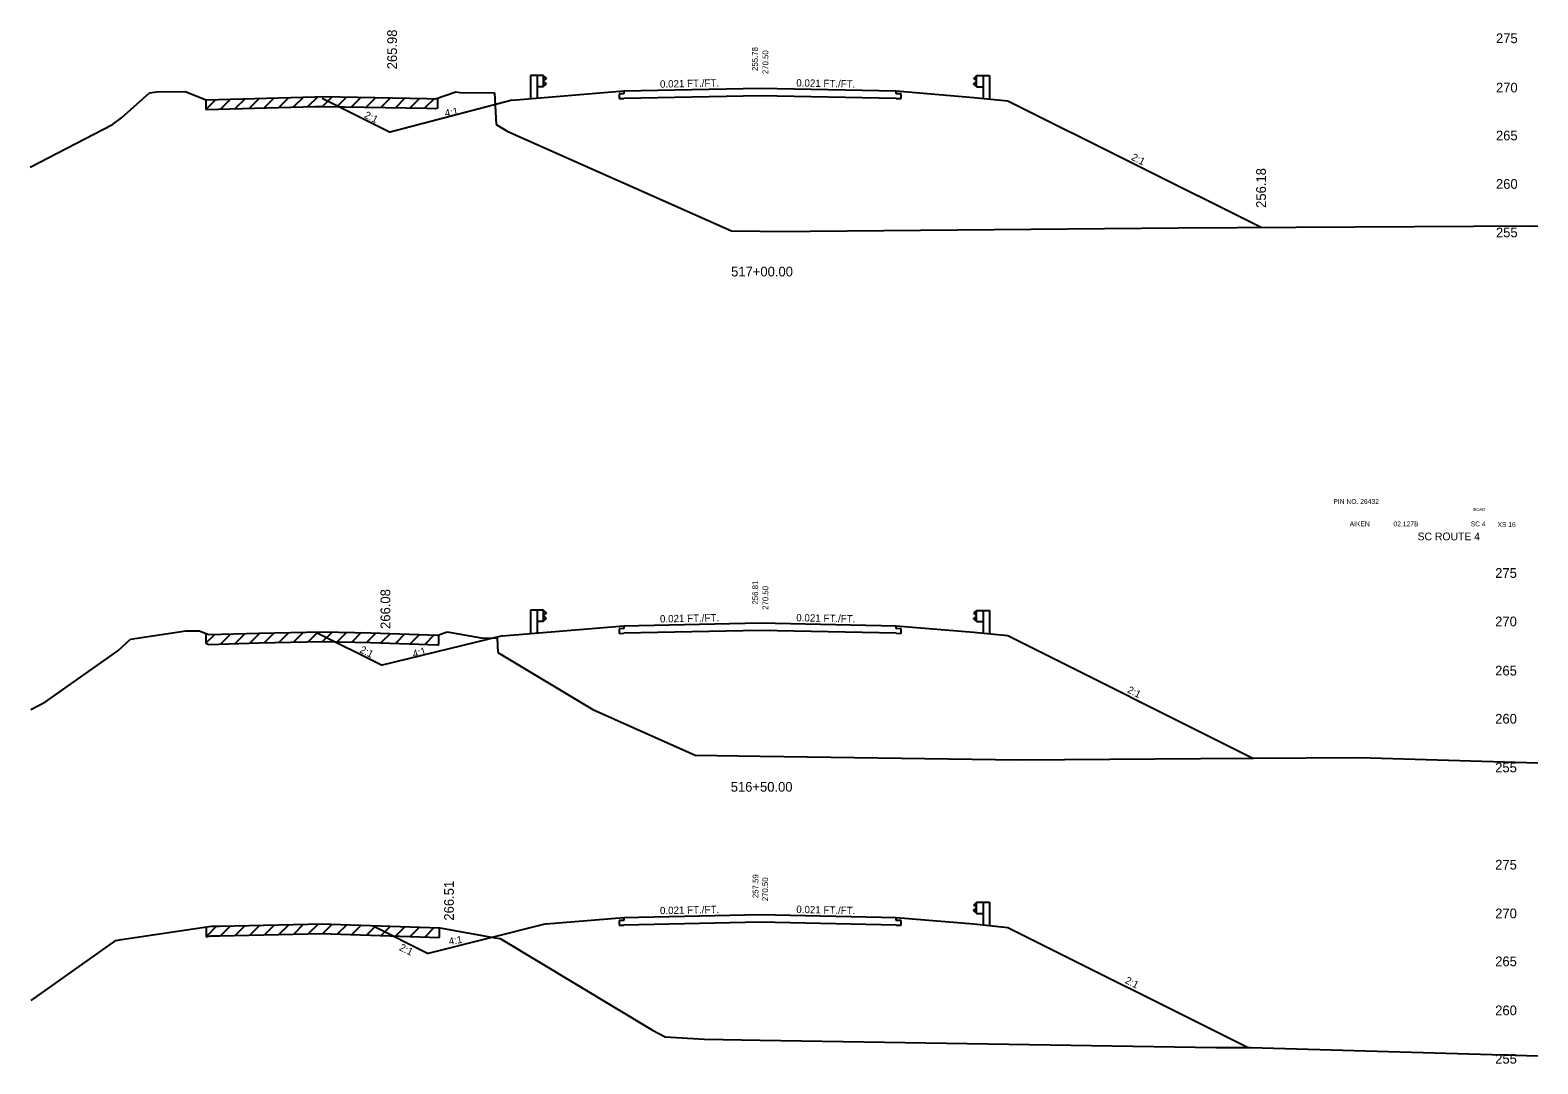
# Model space of a CAD drawing. Extents: x 883 to 1160, y 1002 to 4323.
# Drawn here: x 1004.9 to 1160, y 2770.2 to 2876.5 of the extents above; entities that cross this region are included whole.
import ezdxf

# ---------------------------------------------------------------- set-up
doc = ezdxf.new("R2010")
doc.units = 0
for name, color, linetype in [('Level 1', 7, 'Continuous'), ('Level 10', 7, 'Continuous'), ('Level 11', 7, 'Continuous'), ('Level 12', 7, 'Continuous'), ('Level 24', 7, 'Continuous'), ('Level 3', 7, 'Continuous'), ('Level 32', 7, 'Continuous'), ('Level 33', 7, 'Continuous'), ('Level 59', 7, 'Continuous'), ('Level 6', 7, 'Continuous'), ('Level 60', 7, 'Continuous'), ('Level 61', 7, 'Continuous'), ('Level 7', 7, 'Continuous')]:
    doc.layers.add(name, color=color, linetype=linetype)

msp = doc.modelspace()

# ---------------------------------------------------------------- linework, layer by layer
at = {"layer": 'Level 11'}
for p, q in [((1066, 2869.91), (1065.5, 2869.9)), ((1065.5, 2869.9), (1065.5, 2869.42)), ((1065.5, 2869.42), (1066, 2869.43)), ((1066, 2870.21), (1066, 2869.91)), ((1094, 2869.91), (1094, 2870.21)), ((1094.5, 2869.9), (1094, 2869.91)), ((1094, 2869.43), (1094.5, 2869.42)), ((1094.5, 2869.42), (1094.5, 2869.9)), ((1066, 2814.91), (1065.5, 2814.9)), ((1065.5, 2814.9), (1065.5, 2814.42)), ((1066, 2815.21), (1066, 2814.91)), ((1094, 2814.91), (1094, 2815.21)), ((1094.5, 2814.9), (1094, 2814.91)), ((1094.5, 2814.42), (1094.5, 2814.9)), ((1065.5, 2814.42), (1066, 2814.43)), ((1094, 2814.43), (1094.5, 2814.42)), ((1066, 2784.91), (1065.5, 2784.9)), ((1065.5, 2784.9), (1065.5, 2784.42)), ((1065.5, 2784.42), (1066, 2784.43)), ((1066, 2785.21), (1066, 2784.91)), ((1094, 2784.91), (1094, 2785.21)), ((1094.5, 2784.9), (1094, 2784.91)), ((1094, 2784.43), (1094.5, 2784.42)), ((1094.5, 2784.42), (1094.5, 2784.9))]:
    msp.add_line(p, q, dxfattribs=at)
at = {"layer": 'Level 12'}
for p, q in [((1080, 2869.72), (1066, 2869.43)), ((1094, 2869.43), (1080, 2869.72)), ((1080, 2814.72), (1066, 2814.43)), ((1094, 2814.43), (1080, 2814.72)), ((1080, 2784.72), (1066, 2784.43)), ((1094, 2784.43), (1080, 2784.72))]:
    msp.add_line(p, q, dxfattribs=at)
at = {"layer": 'Level 24'}
for p, q in [((1056.4, 2871.8), (1056.4, 2869.39)), ((1057.07, 2871.8), (1056.4, 2871.8)), ((1057.73, 2871.8), (1057.07, 2871.8)), ((1057.07, 2871.8), (1057.07, 2869.46)), ((1057.73, 2870.64), (1057.07, 2870.64)), ((1057.73, 2870.64), (1057.73, 2871.8)), ((1057.73, 2871.73), (1058, 2871.53)), ((1058, 2871.48), (1057.73, 2871.28)), ((1058, 2870.96), (1057.73, 2871.16)), ((1057.73, 2870.71), (1058, 2870.91)), ((1058, 2871.53), (1058, 2871.48)), ((1058, 2870.91), (1058, 2870.96)), ((1102.27, 2871.72), (1102, 2871.52)), ((1102, 2871.52), (1102, 2871.47)), ((1102, 2871.47), (1102.27, 2871.27)), ((1102, 2870.95), (1102.27, 2871.15)), ((1102, 2870.9), (1102, 2870.95)), ((1102.27, 2870.7), (1102, 2870.9)), ((1102.27, 2870.63), (1102.27, 2871.79)), ((1102.27, 2871.79), (1102.94, 2871.79)), ((1102.27, 2870.63), (1102.94, 2870.63)), ((1102.94, 2871.79), (1102.94, 2869.45)), ((1102.94, 2871.79), (1103.6, 2871.79)), ((1103.6, 2871.79), (1103.6, 2869.38)), ((1056.4, 2816.81), (1056.4, 2814.4)), ((1057.07, 2816.81), (1056.4, 2816.81)), ((1057.73, 2816.81), (1057.07, 2816.81)), ((1057.07, 2816.81), (1057.07, 2814.47)), ((1057.73, 2815.64), (1057.73, 2816.81)), ((1057.73, 2816.74), (1058, 2816.54)), ((1058, 2816.49), (1057.73, 2816.29)), ((1058, 2816.54), (1058, 2816.49)), ((1102.27, 2816.72), (1102, 2816.52)), ((1102, 2816.52), (1102, 2816.47)), ((1102, 2816.47), (1102.27, 2816.27)), ((1102.27, 2815.63), (1102.27, 2816.79)), ((1102.27, 2816.79), (1102.94, 2816.79)), ((1102.94, 2816.79), (1102.94, 2814.45)), ((1102.94, 2816.79), (1103.6, 2816.79)), ((1103.6, 2816.79), (1103.6, 2814.38)), ((1057.73, 2815.64), (1057.07, 2815.64)), ((1058, 2815.97), (1057.73, 2816.17)), ((1057.73, 2815.72), (1058, 2815.92)), ((1058, 2815.92), (1058, 2815.97)), ((1102, 2815.95), (1102.27, 2816.15)), ((1102, 2815.9), (1102, 2815.95)), ((1102.27, 2815.7), (1102, 2815.9)), ((1102.27, 2815.63), (1102.94, 2815.63)), ((1102.27, 2785.63), (1102.27, 2786.79)), ((1102.27, 2786.79), (1102.94, 2786.79)), ((1102.94, 2786.79), (1102.94, 2784.45)), ((1102.94, 2786.79), (1103.6, 2786.79)), ((1103.6, 2786.79), (1103.6, 2784.38)), ((1102.27, 2786.72), (1102, 2786.52)), ((1102, 2786.52), (1102, 2786.47)), ((1102, 2786.47), (1102.27, 2786.27)), ((1102, 2785.95), (1102.27, 2786.15)), ((1102, 2785.9), (1102, 2785.95)), ((1102.27, 2785.7), (1102, 2785.9)), ((1102.27, 2785.63), (1102.94, 2785.63))]:
    msp.add_line(p, q, dxfattribs=at)
at = {"layer": 'Level 59'}
for p, q in [((1066, 2870.21), (1080, 2870.5)), ((1080, 2870.5), (1094, 2870.21)), ((1066, 2815.21), (1080, 2815.5)), ((1080, 2815.5), (1094, 2815.21)), ((1066, 2785.21), (1080, 2785.5)), ((1080, 2785.5), (1094, 2785.21))]:
    msp.add_line(p, q, dxfattribs=at)
at = {"layer": 'Level 6'}
for p, q in [((1054.5, 2869.25), (1066, 2870.21)), ((1094, 2870.21), (1102, 2869.54)), ((1102, 2869.54), (1105.5, 2869.19)), ((1053.5, 2814.17), (1066, 2815.21)), ((1094, 2815.21), (1102, 2814.54)), ((1102, 2814.54), (1105.5, 2814.19)), ((1058, 2784.54), (1066, 2785.21)), ((1094, 2785.21), (1102, 2784.54)), ((1102, 2784.54), (1105.5, 2784.19))]:
    msp.add_line(p, q, dxfattribs=at)
at = {"layer": 'Level 60'}
for p, q in [((1014.32, 2867.43), (1017.18, 2870)), ((1017.18, 2870), (1017.91, 2870.11)), ((1017.91, 2870.11), (1020.87, 2870.15)), ((1020.87, 2870.15), (1023.01, 2869.29)), ((1023.01, 2869.29), (1034.2, 2869.61)), ((1034.2, 2869.61), (1035.02, 2869.62)), ((1035.02, 2869.62), (1045.76, 2869.42)), ((1045.76, 2869.42), (1046.6, 2869.39)), ((1046.6, 2869.39), (1048.72, 2870.13)), ((1048.72, 2870.13), (1049.15, 2870.06)), ((1049.15, 2870.06), (1052.67, 2870.01)), ((1052.67, 2870.01), (1052.85, 2866.76)), ((1004.92, 2862.36), (1013.38, 2866.76)), ((1013.38, 2866.76), (1014.32, 2867.43)), ((1052.85, 2866.76), (1054.06, 2866.03)), ((1054.06, 2866.03), (1077.07, 2855.82)), ((1077.07, 2855.82), (1080, 2855.78)), ((1080, 2855.78), (1081.39, 2855.76)), ((1081.39, 2855.76), (1122.99, 2856.13)), ((1122.99, 2856.13), (1159.46, 2856.32)), ((1159.46, 2856.32), (1160, 2856.3)), ((1013.93, 2812.63), (1015.25, 2813.82)), ((1015.25, 2813.82), (1020.95, 2814.67)), ((1020.95, 2814.67), (1022.31, 2814.69)), ((1022.31, 2814.69), (1023.29, 2814.29)), ((1023.29, 2814.29), (1028.44, 2814.44)), ((1028.44, 2814.44), (1035, 2814.57)), ((1035, 2814.57), (1039.95, 2814.48)), ((1039.95, 2814.48), (1046.84, 2814.25)), ((1046.84, 2814.25), (1047.82, 2814.59)), ((1047.82, 2814.59), (1051.32, 2813.96)), ((1051.32, 2813.96), (1052.95, 2813.94)), ((1052.95, 2813.94), (1053.03, 2812.44)), ((1006.51, 2807.38), (1013.93, 2812.63)), ((1053.03, 2812.44), (1062.8, 2806.59)), ((1005, 2806.59), (1006.51, 2807.38)), ((1062.8, 2806.59), (1073.33, 2801.91)), ((1073.33, 2801.91), (1080, 2801.81)), ((1080, 2801.81), (1106.66, 2801.4)), ((1106.66, 2801.4), (1125.29, 2801.57)), ((1125.29, 2801.57), (1141.62, 2801.66)), ((1141.62, 2801.66), (1160, 2801.12)), ((1014.31, 2782.93), (1023.53, 2784.3)), ((1023.53, 2784.3), (1024.38, 2784.31)), ((1024.38, 2784.31), (1034.99, 2784.54)), ((1034.99, 2784.54), (1035.85, 2784.51)), ((1035.85, 2784.51), (1047.05, 2784.14)), ((1047.05, 2784.14), (1052.74, 2783.12)), ((1005.03, 2776.68), (1013.74, 2782.85)), ((1013.74, 2782.85), (1014.31, 2782.93)), ((1052.74, 2783.12), (1053.25, 2783.03)), ((1053.25, 2783.03), (1068.94, 2773.62)), ((1068.94, 2773.62), (1070.25, 2772.92)), ((1070.25, 2772.92), (1074.27, 2772.69)), ((1074.27, 2772.69), (1080, 2772.59)), ((1080, 2772.59), (1126.87, 2771.84)), ((1126.87, 2771.84), (1130.48, 2771.83)), ((1130.48, 2771.83), (1160, 2770.98))]:
    msp.add_line(p, q, dxfattribs=at)
at = {"layer": 'Level 61'}
for p, q in [((1024.01, 2869.32), (1022.99, 2868.3)), ((1022.99, 2869.3), (1022.99, 2868.3)), ((1025.52, 2869.36), (1024.49, 2868.33)), ((1027.02, 2869.4), (1025.99, 2868.37)), ((1028.52, 2869.45), (1027.49, 2868.42)), ((1030.02, 2869.49), (1028.99, 2868.46)), ((1031.52, 2869.53), (1030.49, 2868.5)), ((1033.02, 2869.57), (1031.99, 2868.54)), ((1034.51, 2869.61), (1033.49, 2868.59)), ((1035.97, 2869.6), (1034.99, 2868.62)), ((1037.47, 2869.58), (1036.49, 2868.59)), ((1038.97, 2869.55), (1037.99, 2868.57)), ((1040.47, 2869.52), (1039.49, 2868.54)), ((1041.97, 2869.49), (1040.99, 2868.51)), ((1043.47, 2869.46), (1042.49, 2868.48)), ((1044.97, 2869.43), (1043.99, 2868.45)), ((1046.46, 2869.4), (1045.49, 2868.42)), ((1046.86, 2868.48), (1046.86, 2869.48)), ((1022.99, 2868.3), (1023.01, 2868.29)), ((1023.01, 2868.29), (1034.2, 2868.61)), ((1034.2, 2868.61), (1035.02, 2868.62)), ((1035.02, 2868.62), (1045.76, 2868.42)), ((1045.76, 2868.42), (1046.6, 2868.39)), ((1046.6, 2868.39), (1046.86, 2868.48)), ((1023, 2814.41), (1023, 2813.41)), ((1023.9, 2814.31), (1023, 2813.41)), ((1023, 2813.41), (1023.29, 2813.29)), ((1023.29, 2813.29), (1028.44, 2813.44)), ((1025.53, 2814.35), (1024.5, 2813.32)), ((1027.03, 2814.4), (1026, 2813.37)), ((1028.53, 2814.44), (1027.5, 2813.41)), ((1028.44, 2813.44), (1035, 2813.57)), ((1030.02, 2814.47), (1029, 2813.45)), ((1031.52, 2814.5), (1030.5, 2813.48)), ((1033.02, 2814.53), (1032, 2813.51)), ((1034.52, 2814.56), (1033.5, 2813.54)), ((1035.98, 2814.55), (1035, 2813.57)), ((1035, 2813.57), (1039.95, 2813.48)), ((1037.48, 2814.53), (1036.5, 2813.54)), ((1038.98, 2814.5), (1038, 2813.52)), ((1040.47, 2814.46), (1039.5, 2813.49)), ((1039.95, 2813.48), (1046.84, 2813.25)), ((1041.97, 2814.41), (1041, 2813.44)), ((1043.47, 2814.36), (1042.5, 2813.39)), ((1044.97, 2814.31), (1044, 2813.34)), ((1046.47, 2814.26), (1045.5, 2813.29)), ((1046.84, 2813.25), (1046.94, 2813.28)), ((1046.94, 2813.28), (1046.94, 2814.28)), ((1024.1, 2784.31), (1023.01, 2783.22)), ((1023.01, 2784.22), (1023.01, 2783.22)), ((1025.53, 2784.34), (1024.51, 2783.32)), ((1027.03, 2784.37), (1026.01, 2783.35)), ((1028.53, 2784.4), (1027.51, 2783.38)), ((1030.03, 2784.43), (1029.01, 2783.41)), ((1031.53, 2784.46), (1030.51, 2783.44)), ((1033.03, 2784.5), (1032.01, 2783.47)), ((1034.53, 2784.53), (1033.51, 2783.51)), ((1035.98, 2784.51), (1035.01, 2783.54)), ((1037.48, 2784.46), (1036.51, 2783.49)), ((1038.98, 2784.41), (1038.01, 2783.44)), ((1040.48, 2784.36), (1039.51, 2783.39)), ((1041.98, 2784.31), (1041.01, 2783.34)), ((1043.48, 2784.26), (1042.51, 2783.29)), ((1044.98, 2784.21), (1044.01, 2783.24)), ((1046.48, 2784.16), (1045.51, 2783.19)), ((1047.02, 2783.14), (1047.02, 2784.14)), ((1023.01, 2783.22), (1023.53, 2783.3)), ((1023.53, 2783.3), (1024.38, 2783.31)), ((1024.38, 2783.31), (1034.99, 2783.54)), ((1034.99, 2783.54), (1035.85, 2783.51)), ((1035.85, 2783.51), (1047.02, 2783.14))]:
    msp.add_line(p, q, dxfattribs=at)
at = {"layer": 'Level 7'}
for p, q in [((1034.94, 2869.47), (1041.95, 2865.96)), ((1054.5, 2869.25), (1041.95, 2865.96)), ((1105.5, 2869.19), (1131.53, 2856.18)), ((1034.32, 2814.56), (1041.14, 2811.15)), ((1053.5, 2814.17), (1041.14, 2811.15)), ((1105.5, 2814.19), (1130.68, 2801.6)), ((1040.13, 2784.37), (1045.85, 2781.51)), ((1058, 2784.54), (1045.85, 2781.51)), ((1105.5, 2784.19), (1130.22, 2771.83))]:
    msp.add_line(p, q, dxfattribs=at)

# ---------------------------------------------------------------- texts
at = {"layer": 'Level 1'}
for s, height, p in [('517+00.00', 1, (1077.02, 2851.13)), ('PIN NO. 26432', 0.5, (1138.97, 2827.74)), ('AIKEN', 0.5, (1140.64, 2825.43)), ('02.127B', 0.5, (1145.15, 2825.43)), ('SC 4', 0.5, (1153.09, 2825.43)), ('XS 16', 0.5, (1155.85, 2825.36)), ('SC ROUTE 4', 0.8, (1147.63, 2823.99)), ('516+50.00', 1, (1076.98, 2798.14))]:
    msp.add_text(s, height=height, dxfattribs=at).set_placement(p)
at = {"layer": 'Level 10'}
for s, p in [('255.78', (1079.77, 2872.26)), ('256.81', (1079.8, 2817.39)), ('257.59', (1079.83, 2787.19))]:
    msp.add_text(s, height=0.6, rotation=90, dxfattribs=at).set_placement(p)
at = {"layer": 'Level 3'}
for s, height, p in [(' 275', 1, (1155.32, 2875.12)), (' 270', 1, (1155.32, 2870.05)), (' 265', 1, (1155.32, 2865.12)), (' 260', 1, (1155.32, 2860.14)), (' 255', 1, (1155.32, 2855.15)), ('ROAD', 0.3, (1153.38, 2827.02)), (' 275', 1, (1155.24, 2820.13)), (' 270', 1, (1155.24, 2815.15)), (' 265', 1, (1155.24, 2810.09)), (' 260', 1, (1155.24, 2805.14)), (' 255', 1, (1155.24, 2800.13)), (' 275', 1, (1155.24, 2790.13)), (' 270', 1, (1155.24, 2785.12)), (' 265', 1, (1155.24, 2780.19)), (' 260', 1, (1155.24, 2775.15)), (' 255', 1, (1155.24, 2770.17))]:
    msp.add_text(s, height=height, dxfattribs=at).set_placement(p)
at = {"layer": 'Level 32'}
for s, rotation, p in [('0.021 FT./FT.', 1.1916, (1069.71, 2870.54)), ('0.021 FT./FT.', 358.8084, (1083.72, 2870.67)), ('2:1', 333.435, (1039.22, 2867.49)), ('4:1', 9.4623, (1047.63, 2867.54)), ('2:1', 333.435, (1118.12, 2863.16)), ('0.021 FT./FT.', 1.1916, (1069.71, 2815.54)), ('0.021 FT./FT.', 358.8084, (1083.72, 2815.67)), ('2:1', 333.435, (1038.75, 2812.51)), ('4:1', 15.9089, (1044.38, 2811.92)), ('2:1', 333.435, (1117.7, 2808.37)), ('0.021 FT./FT.', 1.1916, (1069.71, 2785.54)), ('0.021 FT./FT.', 358.8084, (1083.72, 2785.67)), ('2:1', 333.435, (1042.82, 2781.88)), ('4:1', 9.4623, (1048.04, 2782.37)), ('2:1', 333.435, (1117.47, 2778.49))]:
    msp.add_text(s, height=0.75, rotation=rotation, dxfattribs=at).set_placement(p)
at = {"layer": 'Level 33'}
for s, p in [('265.98', (1042.65, 2872.43)), ('256.18', (1132.03, 2858.18)), ('266.08', (1041.96, 2814.88)), ('266.51', (1048.5, 2784.88))]:
    msp.add_text(s, height=1, rotation=90, dxfattribs=at).set_placement(p)
at = {"layer": 'Level 59'}
for p in [(1080.85, 2871.71), (1080.85, 2816.62), (1080.82, 2786.65)]:
    msp.add_text(' 270.50', height=0.6, rotation=90, dxfattribs=at).set_placement(p)

doc.saveas('drawing.dxf')
